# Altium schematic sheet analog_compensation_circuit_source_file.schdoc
size 315 x 399 mm
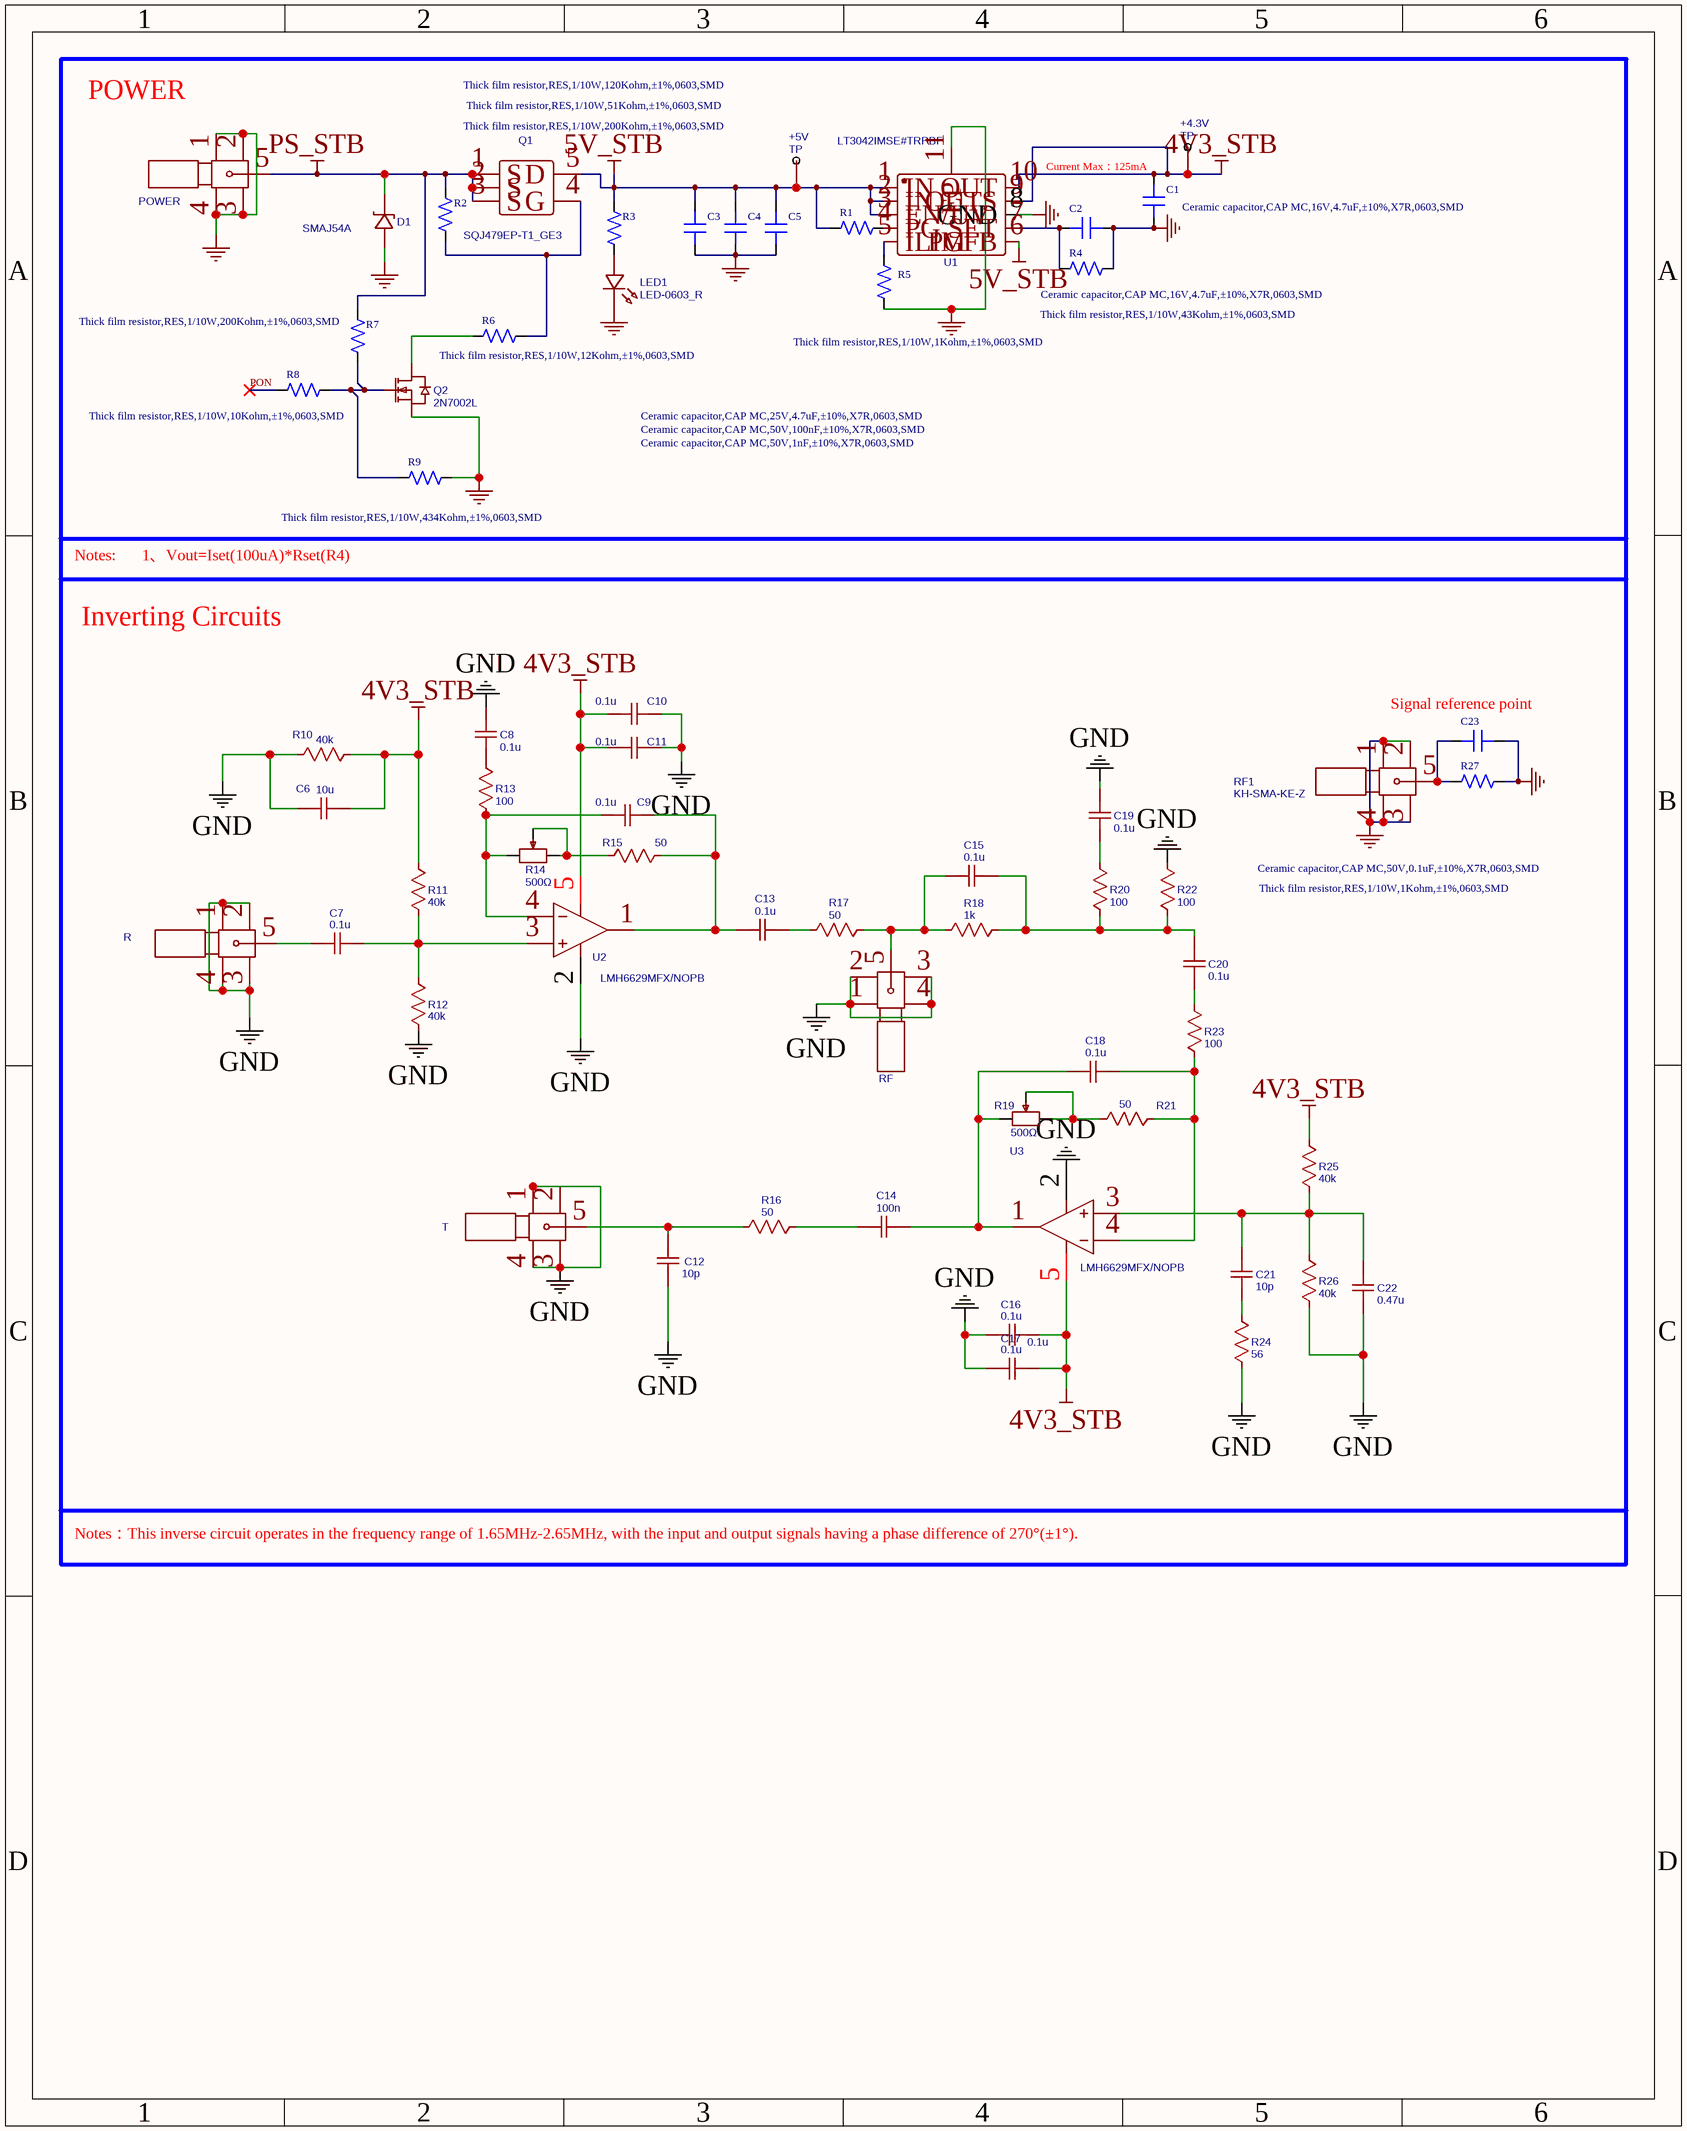
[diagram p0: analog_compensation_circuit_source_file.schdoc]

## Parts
+4.3V  TP  [TP_2MM]
+5V  TP  [TP_2MM]
C1  Ceramic capacitor,CAP MC,16V,4.7uF,±10%,X7R,0603,SMD  [C0603]
C2  Ceramic capacitor,CAP MC,16V,4.7uF,±10%,X7R,0603,SMD  [C0603]
C3  Ceramic capacitor,CAP MC,25V,4.7uF,±10%,X7R,0603,SMD  [C0603]
C4  Ceramic capacitor,CAP MC,50V,100nF,±10%,X7R,0603,SMD  [C0603]
C5  Ceramic capacitor,CAP MC,50V,1nF,±10%,X7R,0603,SMD  [C0603]
C6  10u  [C0603]
C7  0.1u  [C0603]
C8  0.1u  [C0603]
C9  0.1u  [C0603]
C10  0.1u  [C0603]
C11  0.1u  [C0603]
C12  10p  [C0603]
C13  0.1u  [C0603]
C14  100n  [C0603]
C15  0.1u  [C0603]
C16  0.1u  [C0603]
C17  0.1u  [C0603]
C18  0.1u  [C0603]
C19  0.1u  [C0603]
C20  0.1u  [C0603]
C21  10p  [C0603]
C22  0.47u  [C0603]
C23  Ceramic capacitor,CAP MC,50V,0.1uF,±10%,X7R,0603,SMD  [C0603]
D1  SMAJ54A  [SMA_L4.3-W2.6-LS5.0-RD]
LED1  LED-0603_R  [LED0603_RED]
POWER  KH-SMA-KE-Z  [SMA-TH_KH-SMA-KE-Z]  (value not drawn)
Q1  SQJ479EP-T1_GE3  [POWER-SO8_L4.9-W4.4-P1.27-LS6.2-BL]
Q2  2N7002L  [SOT-23-3_L2.9-W1.3-P1.90-LS2.4-BR]
R  KH-SMA-KE-Z  [SMA-TH_KH-SMA-KE-Z]  (value not drawn)
R1  Thick film resistor,RES,1/10W,200Kohm,±1%,0603,SMD  [R0603]
R2  Thick film resistor,RES,1/10W,120Kohm,±1%,0603,SMD  [R0603]
R3  Thick film resistor,RES,1/10W,51Kohm,±1%,0603,SMD  [R0603]
R4  Thick film resistor,RES,1/10W,43Kohm,±1%,0603,SMD  [R0603]
R5  Thick film resistor,RES,1/10W,1Kohm,±1%,0603,SMD  [R0603]
R6  Thick film resistor,RES,1/10W,12Kohm,±1%,0603,SMD  [R0603]
R7  Thick film resistor,RES,1/10W,200Kohm,±1%,0603,SMD  [R0603]
R8  Thick film resistor,RES,1/10W,10Kohm,±1%,0603,SMD  [R0603]
R9  Thick film resistor,RES,1/10W,434Kohm,±1%,0603,SMD  [R0603]
R10  40k  [R0603]
R11  40k  [R0603]
R12  40k  [R0603]
R13  100  [R0603]
R14  500Ω  [RES-ADJ-SMD_3224W]
R15  50  [R0603]
R16  50  [R0603]
R17  50  [R0603]
R18  1k  [R0603]
R19  500Ω  [RES-ADJ-SMD_3224W]
R20  100  [R0603]
R21  50  [R0603]
R22  100  [R0603]
R23  100  [R0603]
R24  56  [R0603]
R25  40k  [R0603]
R26  40k  [R0603]
R27  Thick film resistor,RES,1/10W,1Kohm,±1%,0603,SMD  [R0603]
RF  KH-SMA-KE-Z  [SMA-TH_KH-SMA-KE-Z]  (value not drawn)
RF1  KH-SMA-KE-Z  [SMA-TH_KH-SMA-KE-Z]
T  KH-SMA-KE-Z  [SMA-TH_KH-SMA-KE-Z]  (value not drawn)
U1  LT3042IMSE#TRPBF  [MSOP-10_L3.0-W3.0-P0.50-LS5.0-BL-EP]
U2  LMH6629MFX/NOPB  [SOT-23-5_L2.9-W1.6-P0.95-LS2.8-BR]
U3  LMH6629MFX/NOPB  [SOT-23-5_L2.9-W1.6-P0.95-LS2.8-BR]

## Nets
4V3_STB: +4.3V.1 C1.1 C6.2 C10.1 C11.1 C16.1 C17.1 R10.2 R11.2 R25.2 U1.9(OUTS) U1.10(OUT) U2.5(V+) U3.5(V+)
5V_STB: +5V.1 C3.2 C4.2 C5.2 Q1.5(D) R1.2 R3.2 U1.1(IN) U1.2(IN) U1.3(EN/UV) U1.6(PGFB)
GND: C1.2 C2.1 C3.1 C4.1 C5.1 C6.1 C8.2 C10.2 C11.2 C12.1 C16.2 C17.2 C19.2 C22.1 C23.1 D1.2(A) LED1.2 POWER.1 POWER.2 POWER.3 POWER.4 Q2.2(S) R.1 R.2 R.3 R.4 R4.1 R5.1 R9.2 R10.1 R12.1 R22.2 R24.1 R26.1 R27.1 RF.1 RF.2 RF.3 RF.4 RF1.1 RF1.2 RF1.3 RF1.4 T.1 T.2 T.3 T.4 U1.8(GND) U1.11(EP) U2.2(V-) U3.2(V-)
PS_STB: D1.1(K) POWER.5 Q1.1(S) Q1.2(S) Q1.3(S) R2.2 R7.2
PON: R8.1
NetC2_2: C2.2 R4.2 U1.7(SET)
NetC7_1: C7.1 R.5
NetC7_2: C7.2 R11.1 R12.2 U2.3(+IN)
NetC8_1: C8.1 R13.2
NetC9_1: C9.1 R13.1 R14.3 U2.4(-IN)
NetC9_2: C9.2 C13.1 R15.2 U2.1(OUT)
NetC12_2: C12.2 R16.1 T.5
NetC13_2: C13.2 R17.1
NetC14_1: C14.1 R16.2
NetC14_2: C14.2 C18.1 R19.3 U3.1(OUT)
NetC15_1: C15.1 R17.2 R18.1 RF.5
NetC15_2: C15.2 C20.2 R18.2 R20.1 R22.1
NetC18_2: C18.2 R21.2 R23.1 U3.4(-IN)
NetC19_1: C19.1 R20.2
NetC20_1: C20.1 R23.2
NetC21_1: C21.1 R24.2
NetC21_2: C21.2 C22.2 R25.1 R26.2 U3.3(+IN)
NetC23_2: C23.2 R27.2 RF1.5
NetLED1_1: LED1.1 R3.1
NetQ1_4: Q1.4(G) R2.1 R6.2
NetQ2_1: Q2.1(G) R7.1 R8.2 R9.1
NetQ2_3: Q2.3(D) R6.1
NetR1_1: R1.1 U1.4(PG)
NetR5_2: R5.2 U1.5(ILIM)
NetR14_1: R14.1 R14.2 R15.1
NetR19_1: R19.1 R19.2 R21.1

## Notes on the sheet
- POWER
- (near C1) Current Max：125mA
- Notes:
- 1、Vout=Iset(100uA)*Rset(R4)
- Inverting Circuits
- (near C23) Signal reference point
- (near C16) 0.1u
- Notes：This inverse circuit operates in the frequency range of 1.65MHz-2.65MHz, with the input and output signals having a phase difference of 270°(±1°).

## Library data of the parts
+4.3V +5V = TP: Manufacturer: 盈帜; Contributor: 袁明月
C6 = 10u: nameAlias: Value(F); Contributor: LCEDA_Lib
C7-C11 C13 C15-C20 = 0.1u: nameAlias: Value(F); Contributor: LCEDA_Lib
C12 C21 = 10p: nameAlias: Value(F); Contributor: LCEDA_Lib
C14 = 100n: nameAlias: Value(F); Contributor: LCEDA_Lib
C22 = 0.47u: nameAlias: Value(F); Contributor: LCEDA_Lib
D1 = SMAJ54A: Manufacturer: Littelfuse(美国力特); Contributor: LCSC
LED1 = LED-0603_R: Manufacturer: EVERLIGHT(台湾亿光); Manufacturer Part: 19-217/R6C-AL1M2VY/3T; Contributor: LCEDA_01
POWER R RF RF1 T = KH-SMA-KE-Z: Manufacturer: kinghelm(金航标); Contributor: LCSC
Q1 = SQJ479EP-T1_GE3: Manufacturer: VISHAY(威世); Contributor: LCSC
Q2 = 2N7002L: Manufacturer: onsemi(安森美); Contributor: LCSC
R10-R12 R25 R26 = 40k: nameAlias: Value(Ω); Contributor: LCEDA_Lib
R13 R20 R22 R23 = 100: nameAlias: Value(Ω); Contributor: LCEDA_Lib
R14 R19 = 500Ω: Manufacturer: BOURNS; Manufacturer Part: 3224W-1-501E; Resistance(Ohms): 500; nameAlias: Value; Contributor: LCSC
R15-R17 R21 = 50: nameAlias: Value(Ω); Contributor: LCEDA_Lib
R18 = 1k: nameAlias: Value(Ω); Contributor: LCEDA_Lib
R24 = 56: nameAlias: Value(Ω); Contributor: LCEDA_Lib
U1 = LT3042IMSE#TRPBF: Manufacturer: ADI(亚德诺); Contributor: LCSC
U2 U3 = LMH6629MFX/NOPB: Manufacturer: TI(德州仪器); Contributor: LCSC; Package Display: No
